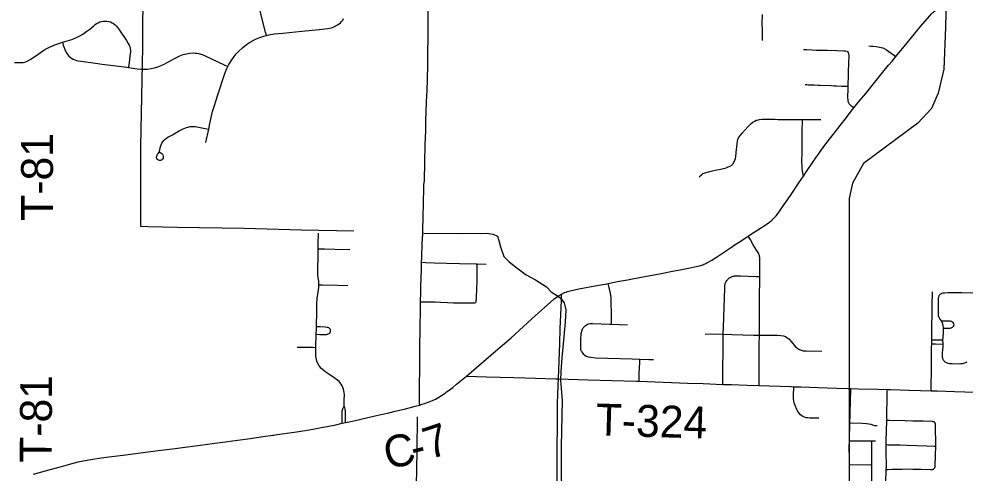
# Model space of a CAD drawing. Extents: x 0 to 680, y 0 to 834.
# Drawn here: x 268.3 to 333.1, y 304.5 to 335.6 of the extents above; entities that cross this region are included whole.
import ezdxf

# ---------------------------------------------------------------- set-up
doc = ezdxf.new("R2010")
doc.units = 0
for name, color, linetype in [('GM_X_City_Street', 7, 'Continuous'), ('GM_X_County_Road', 7, 'Continuous'), ('GM_X_County_Road_Text', 7, 'Continuous'), ('GM_X_Minor_River', 7, 'Continuous'), ('GM_X_Rail_Line', 7, 'Continuous'), ('GM_X_Township_Road', 7, 'Continuous'), ('GM_X_Township_Road_Text', 7, 'Continuous')]:
    doc.layers.add(name, color=color, linetype=linetype)

msp = doc.modelspace()

# ---------------------------------------------------------------- linework, layer by layer
at = {"layer": 'GM_X_City_Street'}
msp.add_line((326.659, 306.718), (326.942, 306.715), dxfattribs=at)
for points in [[(285.264, 334.424), (285.207, 334.647), (284.771, 336.356)], [(268.025, 332.57), (268.505, 332.574), (268.622, 332.582), (268.734, 332.602), (268.844, 332.638), (268.951, 332.684), (269.156, 332.801), (269.651, 333.136), (270.044, 333.413), (270.251, 333.538), (270.467, 333.648), (270.801, 333.787), (271.143, 333.904), (271.308, 333.956), (271.943, 334.157), (272.275, 334.287), (272.489, 334.39), (272.695, 334.507), (272.99, 334.707), (273.177, 334.854), (273.449, 335.09), (273.544, 335.166), (273.645, 335.236), (273.752, 335.297), (273.865, 335.346), (273.984, 335.382), (274.107, 335.403), (274.231, 335.41), (274.354, 335.403), (274.477, 335.382), (274.595, 335.345), (274.709, 335.294), (274.815, 335.231), (274.913, 335.155), (275.002, 335.069), (275.082, 334.976), (275.222, 334.777), (275.692, 334.08), (275.816, 333.871), (275.869, 333.761), (275.912, 333.645), (275.941, 333.525), (275.957, 333.403), (275.957, 333.28), (275.931, 333.037), (275.866, 332.563), (275.854, 332.444), (275.833, 332.23)], [(281.132, 327.117), (281.325, 328.027), (281.404, 328.403), (281.586, 329.219), (281.681, 329.564), (281.941, 330.359), (282.43, 331.834), (282.561, 332.167), (282.626, 332.302), (282.664, 332.383), (282.846, 332.691), (283.052, 332.985), (283.204, 333.17), (283.368, 333.343), (283.632, 333.586), (283.913, 333.809), (284.11, 333.944), (284.315, 334.065), (284.529, 334.172), (284.749, 334.265), (285.089, 334.38), (285.264, 334.424), (285.436, 334.467), (285.789, 334.528), (286.384, 334.589), (287.692, 334.72), (288.882, 334.833), (289.475, 334.901), (289.71, 334.947), (289.823, 334.984), (289.932, 335.033), (290.14, 335.15), (290.237, 335.22), (290.327, 335.298), (290.41, 335.385), (290.484, 335.479), (290.548, 335.579)], [(319.2, 334.091), (319.2, 334.793), (319.196, 335.228), (319.212, 335.865)], [(271.308, 333.956), (271.371, 333.752), (271.407, 333.638), (271.489, 333.412), (271.542, 333.304), (271.603, 333.201), (271.674, 333.105), (271.754, 333.016), (271.843, 332.935), (271.94, 332.866), (272.044, 332.807), (272.155, 332.76), (272.269, 332.724), (272.386, 332.697), (272.742, 332.647), (273.57, 332.525), (274.03, 332.465), (275.713, 332.247), (275.833, 332.23), (276.425, 332.146), (276.663, 332.119), (276.902, 332.113), (277.141, 332.128), (277.379, 332.16), (277.614, 332.208), (277.844, 332.275), (278.066, 332.364), (278.281, 332.471), (279.019, 332.871), (279.341, 333.031), (279.564, 333.118), (279.679, 333.153), (279.796, 333.179), (280.033, 333.213), (280.272, 333.226), (280.392, 333.222), (280.511, 333.209), (280.63, 333.189), (280.862, 333.129), (281.084, 333.04), (282.382, 332.419), (282.626, 332.302)], [(322.008, 333.474), (322.245, 333.461), (322.604, 333.442), (322.903, 333.427), (323.625, 333.416), (324.285, 333.389), (324.765, 333.376), (324.881, 333.364), (324.991, 333.34), (325.035, 333.316), (325.059, 333.294)], [(326.484, 333.705), (326.634, 333.699), (326.751, 333.693), (326.988, 333.669), (327.337, 333.612), (327.446, 333.581), (327.544, 333.536), (327.688, 333.448), (327.853, 333.329), (328.022, 333.207), (328.234, 333.054), (328.331, 332.984)], [(325.464, 329.471), (325.317, 329.577), (325.261, 329.618), (325.222, 329.654), (325.182, 329.703), (325.146, 329.756), (325.116, 329.807), (325.092, 329.861), (325.073, 329.917), (325.061, 330.019), (325.055, 330.17), (325.055, 330.385), (325.064, 330.597), (325.07, 330.954), (325.086, 331.747), (325.096, 332.086), (325.111, 332.402), (325.117, 332.683), (325.127, 332.866), (325.129, 333.04), (325.124, 333.185), (325.098, 333.248), (325.059, 333.294)], [(322.129, 331.073), (322.246, 331.064), (322.347, 331.061), (322.451, 331.058), (322.62, 331.051), (322.732, 331.048), (323.017, 331.038), (323.133, 331.032), (323.9, 330.995), (324.082, 330.991), (324.265, 330.985), (324.609, 330.969), (324.979, 330.957), (325.07, 330.954)], [(314.875, 324.765), (315.055, 324.922), (315.136, 324.979), (315.223, 325.022), (315.279, 325.042), (315.507, 325.112), (315.972, 325.222), (316.442, 325.31), (316.713, 325.387), (316.865, 325.434), (316.932, 325.469), (317.034, 325.521), (317.082, 325.554), (317.127, 325.591), (317.168, 325.634), (317.205, 325.68), (317.268, 325.782), (317.318, 325.89), (317.353, 326.004), (317.376, 326.122), (317.411, 326.418), (317.476, 327.012), (317.502, 327.189), (317.531, 327.305), (317.575, 327.416), (317.632, 327.52), (317.702, 327.617), (317.818, 327.753), (318.222, 328.194), (318.393, 328.359), (318.574, 328.514), (318.675, 328.577), (318.783, 328.626), (318.84, 328.643), (319.014, 328.685), (319.189, 328.709), (319.36, 328.709), (319.559, 328.704), (319.841, 328.705), (320.08, 328.7), (320.259, 328.691), (320.464, 328.69), (320.851, 328.682), (321.139, 328.685), (321.437, 328.676), (321.636, 328.676), (321.797, 328.671), (321.949, 328.671), (322.008, 328.671), (322.118, 328.674), (322.347, 328.683), (322.513, 328.676), (322.692, 328.681), (322.825, 328.681), (323.058, 328.686), (323.195, 328.681)], [(322.012, 324.817), (321.977, 325.032), (321.929, 325.327), (321.915, 325.449), (321.906, 325.811), (321.921, 326.449), (321.921, 326.786), (321.921, 327.027), (321.926, 327.392), (321.93, 328.041), (321.948, 328.41), (321.948, 328.528), (321.949, 328.671)], [(277.944, 326.458), (278.047, 326.391), (278.104, 326.348), (278.147, 326.306), (278.171, 326.269), (278.187, 326.232), (278.202, 326.154), (278.202, 326.085), (278.191, 326.037), (278.16, 325.977), (278.122, 325.941), (278.077, 325.907), (278.018, 325.884), (277.952, 325.88), (277.902, 325.891), (277.844, 325.92), (277.804, 325.957), (277.772, 326.007), (277.756, 326.063), (277.752, 326.125), (277.765, 326.182), (277.784, 326.236), (277.818, 326.287), (277.887, 326.385), (277.926, 326.443), (277.946, 326.488), (277.979, 326.602), (277.994, 326.72), (278.02, 326.836), (278.06, 326.948), (278.113, 327.055), (278.179, 327.153), (278.256, 327.244), (278.341, 327.327), (278.433, 327.403), (278.532, 327.469), (278.845, 327.641), (279.26, 327.875), (279.577, 328.039), (279.796, 328.133), (279.91, 328.167), (280.026, 328.191), (280.145, 328.204), (280.264, 328.207), (280.382, 328.201), (280.5, 328.186), (281.085, 328.073), (281.325, 328.027)], [(290.588, 309.082), (290.596, 309.548), (290.602, 309.846), (290.59, 310.025), (290.57, 310.143), (290.54, 310.258), (290.498, 310.37), (290.446, 310.477), (290.385, 310.58), (290.315, 310.677), (290.236, 310.766), (290.148, 310.846), (289.906, 311.022), (289.46, 311.321), (289.265, 311.46), (289.078, 311.608), (288.994, 311.692), (288.92, 311.786), (288.854, 311.886), (288.768, 312.043), (288.72, 312.152), (288.685, 312.266), (288.661, 312.383), (288.646, 312.501), (288.642, 312.621), (288.652, 312.979), (288.652, 313.104), (288.653, 313.397), (288.668, 313.755), (288.676, 313.999), (288.689, 314.351), (288.691, 314.509), (288.709, 315.605), (288.723, 316.082), (288.748, 316.439), (288.783, 316.735), (288.833, 317.029), (288.851, 317.208), (288.856, 317.382), (288.858, 317.446), (288.85, 317.625), (288.814, 317.861), (288.79, 318.039), (288.785, 318.158), (288.804, 319.59), (288.802, 319.71), (288.805, 319.769), (288.807, 319.851), (288.814, 320.187), (288.832, 320.903)], [(318.992, 313.929), (319.001, 314.973), (319.014, 316.349), (319.018, 317.938), (319.029, 318.762), (319.033, 319.094), (319.031, 319.164), (319.026, 319.237), (319.014, 319.306), (319, 319.368), (318.983, 319.427), (318.958, 319.486), (318.931, 319.545), (318.904, 319.595), (318.802, 319.756), (318.581, 320.116), (318.355, 320.495), (318.226, 320.711)], [(288.807, 319.851), (289.06, 319.848), (289.238, 319.846), (289.953, 319.824), (290.966, 319.805)], [(316.498, 310.577), (316.499, 310.786), (316.504, 311.659), (316.51, 312.859), (316.518, 313.802), (316.523, 314.013), (316.535, 314.49), (316.582, 315.826), (316.625, 317.161), (316.64, 317.347), (316.65, 317.407), (316.662, 317.459), (316.68, 317.516), (316.701, 317.565), (316.728, 317.616), (316.757, 317.664), (316.789, 317.708), (316.828, 317.753), (316.867, 317.793), (316.911, 317.83), (316.95, 317.859), (316.988, 317.883), (317.035, 317.909), (317.087, 317.933), (317.144, 317.954), (317.195, 317.969), (317.243, 317.977), (317.284, 317.986), (317.352, 317.992), (317.424, 317.994), (317.708, 317.993), (318.781, 317.947), (319.018, 317.938)], [(288.856, 317.382), (289.106, 317.375), (290.12, 317.349), (290.836, 317.335)], [(308.866, 314.695), (308.868, 314.797), (308.875, 315.352), (308.864, 316.26), (308.848, 316.501), (308.801, 316.81), (308.699, 317.282), (308.657, 317.477)], [(305.255, 310.947), (305.272, 311.592), (305.333, 313.342), (305.375, 314.383), (305.434, 315.818), (305.456, 316.342), (305.454, 316.746)], [(330.749, 310.137), (330.751, 310.265), (330.769, 311.71), (330.777, 313.082), (330.783, 313.349), (330.788, 313.616), (330.796, 313.977), (330.818, 315.947), (330.829, 316.902)], [(333.604, 316.815), (332.848, 316.825), (331.892, 316.823), (331.655, 316.82), (331.541, 316.805), (331.486, 316.789), (331.435, 316.77), (331.389, 316.742), (331.346, 316.71), (331.313, 316.67), (331.284, 316.625), (331.249, 316.523), (331.238, 316.47), (331.226, 316.354), (331.223, 315.756), (331.223, 315.397), (331.232, 315.283), (331.263, 315.175), (331.315, 315.077), (331.345, 315.028), (331.447, 314.899), (331.509, 314.775), (331.533, 314.717), (331.552, 314.594), (331.562, 314.428), (331.566, 314.353), (331.562, 314.111), (331.539, 313.79), (331.535, 313.624), (331.545, 313.329)], [(306.817, 312.832), (306.788, 312.924), (306.777, 313.024), (306.774, 313.179), (306.783, 313.635), (306.806, 314.044), (306.836, 314.208), (306.886, 314.343), (306.948, 314.445), (307.027, 314.536), (307.096, 314.594), (307.161, 314.64)], [(307.161, 314.64), (307.217, 314.671), (307.291, 314.702), (307.407, 314.729), (307.573, 314.742), (308.762, 314.699), (308.866, 314.695), (309.974, 314.654)], [(331.562, 314.428), (331.764, 314.423), (331.939, 314.419), (332.056, 314.427), (332.114, 314.439), (332.169, 314.458), (332.219, 314.487), (332.261, 314.526), (332.292, 314.575), (332.309, 314.631), (332.312, 314.655), (332.309, 314.689), (332.302, 314.716), (332.292, 314.745), (332.261, 314.794), (332.219, 314.834), (332.168, 314.862), (332.113, 314.88), (332.055, 314.892), (331.938, 314.901), (331.822, 314.901), (331.447, 314.899)], [(288.676, 313.999), (288.908, 313.994), (289.265, 313.986), (289.385, 313.991), (289.443, 314), (289.5, 314.019), (289.553, 314.047), (289.598, 314.085), (289.632, 314.133), (289.652, 314.189), (289.657, 314.247), (289.645, 314.303), (289.618, 314.355), (289.577, 314.397), (289.528, 314.429), (289.473, 314.453), (289.415, 314.469), (289.296, 314.484), (288.939, 314.499), (288.691, 314.509)], [(315.29, 314.04), (316.523, 314.013), (317.109, 313.991), (318.615, 313.936), (318.992, 313.929)], [(318.981, 310.492), (318.98, 310.65), (318.979, 310.92), (318.983, 311.491), (318.982, 311.8), (318.97, 312.775), (318.979, 313.301), (318.992, 313.929)], [(318.992, 313.929), (320.226, 313.942), (320.467, 313.926), (320.635, 313.893), (320.775, 313.843), (320.884, 313.783), (321, 313.69), (321.164, 313.513), (321.472, 313.152), (321.592, 313.044), (321.726, 312.957), (321.852, 312.904), (321.985, 312.874), (322.206, 312.861), (323.261, 312.851)], [(330.783, 313.349), (331.038, 313.342), (331.545, 313.329)], [(330.788, 313.616), (330.986, 313.616), (331.182, 313.615), (331.312, 313.618), (331.535, 313.624)], [(331.545, 313.329), (331.54, 313.092), (331.524, 312.982), (331.496, 312.686), (331.493, 312.569), (331.502, 312.455), (331.514, 312.4), (331.531, 312.347), (331.553, 312.296), (331.58, 312.247), (331.612, 312.201), (331.649, 312.158), (331.69, 312.12), (331.734, 312.087), (331.782, 312.059), (331.833, 312.037), (331.886, 312.02), (331.998, 312.001), (332.174, 311.994), (332.651, 311.988), (332.767, 311.995), (332.882, 312.013), (333.052, 312.058), (333.218, 312.117)], [(287.377, 313.125), (287.948, 313.115), (288.43, 313.108), (288.652, 313.104)], [(306.817, 312.832), (306.874, 312.749), (306.946, 312.663), (307.048, 312.578), (307.147, 312.512), (307.279, 312.459), (307.466, 312.425), (307.797, 312.398), (310.302, 312.323), (310.819, 312.305), (311.421, 312.283), (311.754, 312.271)], [(310.759, 310.784), (310.771, 311.32), (310.808, 312.09), (310.819, 312.305)], [(323.06, 308.27), (322.454, 308.27), (322.318, 308.281), (322.201, 308.297), (322.085, 308.326), (321.975, 308.372), (321.895, 308.423), (321.806, 308.503), (321.712, 308.611), (321.631, 308.73), (321.564, 308.856), (321.454, 309.121), (321.381, 309.323), (321.36, 309.402), (321.344, 309.484), (321.334, 309.58), (321.338, 309.843), (321.354, 310.36), (321.355, 310.413)], [(325.186, 307.936), (325.201, 308.517), (325.238, 309.566), (325.25, 310.067), (325.255, 310.284)], [(327.708, 308.113), (327.749, 310.099), (327.751, 310.222)], [(290.455, 307.913), (290.453, 308.18), (290.451, 308.561), (290.455, 308.746), (290.488, 308.898), (290.588, 309.082)], [(290.678, 307.962), (290.678, 308.263), (290.678, 308.689), (290.664, 308.903), (290.64, 308.983), (290.588, 309.082)], [(325.155, 306.724), (325.156, 306.751), (325.186, 307.936)], [(325.186, 307.936), (325.232, 307.936), (326.018, 307.925), (326.327, 307.909), (326.492, 307.886), (326.63, 307.851), (326.809, 307.785), (326.875, 307.771), (326.961, 307.759), (327.045, 307.76)], [(327.676, 306.455), (327.678, 306.709), (327.708, 308.113)], [(331.06, 306.359), (331.06, 306.424), (331.059, 306.56), (331.052, 307.599), (331.051, 307.75), (331.049, 307.826), (331.048, 307.853), (331.043, 307.879), (331.035, 307.903), (331.024, 307.925), (331.008, 307.949), (330.991, 307.968), (330.97, 307.988), (330.946, 308.004), (330.921, 308.017), (330.894, 308.025), (330.845, 308.036), (330.808, 308.039), (330.193, 308.053), (329.502, 308.067), (328.978, 308.082), (327.905, 308.108), (327.708, 308.113)], [(325.158, 305.093), (325.152, 305.558), (325.149, 306.226), (325.155, 306.724)], [(325.155, 306.724), (325.855, 306.721), (326.659, 306.718)], [(326.659, 306.718), (326.663, 306.305), (326.674, 305.077)], [(327.68, 304.766), (327.684, 304.913), (327.686, 305.318), (327.678, 305.6), (327.671, 305.925), (327.676, 306.455)], [(327.676, 306.455), (327.775, 306.453), (328.62, 306.433), (329.074, 306.424), (330.437, 306.382), (330.959, 306.362), (331.06, 306.359)], [(327.68, 304.766), (327.794, 304.767), (328.052, 304.769), (328.513, 304.776), (328.761, 304.785), (329.054, 304.795), (329.489, 304.79), (330.06, 304.771), (330.677, 304.754), (330.759, 304.753), (330.791, 304.754), (330.823, 304.756), (330.854, 304.763), (330.883, 304.774), (330.91, 304.786), (330.934, 304.799), (330.957, 304.818), (330.976, 304.84), (330.999, 304.882), (331.008, 304.912), (331.013, 304.941), (331.02, 305.004), (331.048, 305.71), (331.06, 306.359)], [(325.158, 305.093), (325.199, 305.093), (326.587, 305.078), (326.674, 305.077)], [(325.175, 303.124), (325.169, 303.864), (325.163, 304.604), (325.158, 305.093)], [(326.674, 305.077), (326.67, 304.302), (326.666, 303.456), (326.666, 303.269), (326.664, 303.139)], [(327.558, 301.905), (327.562, 302.097), (327.578, 302.933), (327.592, 303.265), (327.626, 303.746), (327.666, 304.455), (327.679, 304.715), (327.68, 304.766)]]:
    msp.add_lwpolyline(points, dxfattribs=at)
at = {"layer": 'GM_X_County_Road'}
msp.add_line((285.763, 307.102), (285.872, 307.118), dxfattribs=at)
for points in [[(328.331, 332.984), (329.099, 333.919), (329.395, 334.289), (330.022, 335.039), (330.626, 335.745), (330.773, 335.899), (330.841, 335.962), (330.913, 336.023), (330.985, 336.077), (331.05, 336.125), (331.108, 336.165)], [(325.464, 329.471), (325.65, 329.707), (325.85, 329.952), (326.268, 330.468), (326.615, 330.894), (327.357, 331.806), (327.84, 332.39), (328.069, 332.665), (328.331, 332.984)], [(322.012, 324.817), (322.214, 325.117), (322.643, 325.755), (322.907, 326.131), (323.032, 326.304), (323.184, 326.517), (323.548, 327.018), (324.131, 327.773), (324.513, 328.262), (324.952, 328.822), (325.286, 329.245), (325.464, 329.471)], [(318.226, 320.711), (318.382, 320.814), (318.882, 321.138), (319.448, 321.495), (319.684, 321.661), (319.854, 321.797), (319.994, 321.931), (320.138, 322.095), (320.298, 322.305), (320.622, 322.78), (320.914, 323.2), (321.21, 323.626), (321.7, 324.353), (322.012, 324.817)], [(308.657, 317.477), (309.298, 317.598), (309.979, 317.718), (311.03, 317.922), (311.662, 318.045), (312.269, 318.164), (313.042, 318.308), (313.582, 318.408), (314.143, 318.521), (314.562, 318.604), (314.89, 318.682), (315.12, 318.753), (315.199, 318.784), (315.277, 318.816), (315.489, 318.921), (315.743, 319.068), (316.063, 319.279), (316.537, 319.6), (317.015, 319.912), (317.349, 320.139), (317.567, 320.281), (318.163, 320.67), (318.226, 320.711)], [(305.454, 316.746), (305.663, 316.846), (305.768, 316.888), (305.861, 316.921), (306.041, 316.971), (306.647, 317.101), (307.866, 317.333), (308.547, 317.457), (308.657, 317.477)], [(298.952, 311.127), (299.79, 311.862), (300.455, 312.427), (300.97, 312.865), (302.005, 313.767), (302.854, 314.532), (303.675, 315.273), (304.283, 315.821), (304.675, 316.169), (304.96, 316.42), (305.05, 316.493), (305.149, 316.565), (305.286, 316.651), (305.454, 316.746)], [(295.753, 309.161), (295.86, 309.19), (296.154, 309.282), (296.407, 309.373), (296.625, 309.464), (296.838, 309.571), (297.071, 309.703), (297.318, 309.863), (297.497, 309.983), (297.593, 310.055), (297.707, 310.14), (298.01, 310.372), (298.274, 310.578), (298.952, 311.127)], [(292.802, 308.439), (293.217, 308.533), (293.636, 308.627), (294.078, 308.733), (294.775, 308.9), (295.537, 309.103), (295.753, 309.161)], [(290.78, 307.984), (290.814, 307.992), (291.244, 308.081), (292.204, 308.304), (292.802, 308.439)], [(285.872, 307.118), (287.162, 307.302), (287.474, 307.347), (288.181, 307.459), (288.557, 307.529), (289.142, 307.639), (289.168, 307.645), (290.007, 307.816), (290.455, 307.913)], [(290.455, 307.913), (290.678, 307.962), (290.78, 307.984)], [(269.337, 304.437), (270.562, 304.776), (271.235, 304.962), (271.889, 305.142), (272.396, 305.275), (272.724, 305.344), (273.401, 305.466), (273.967, 305.547), (274.488, 305.612), (275.46, 305.732), (277.683, 306.027), (279.032, 306.203), (279.695, 306.283), (280.571, 306.4), (281.068, 306.466), (281.73, 306.556), (282.463, 306.658), (282.936, 306.72), (284.001, 306.863), (285.042, 307.003), (285.713, 307.095), (285.763, 307.102)]]:
    msp.add_lwpolyline(points, dxfattribs=at)
at = {"layer": 'GM_X_Minor_River'}
for points in [[(276.813, 345.396), (276.806, 338.087), (276.778, 333.623), (276.641, 326.854), (276.654, 321.383), (277.164, 321.367), (279.16, 321.332), (283.734, 321.245), (287.668, 321.13), (291.252, 321.076)], [(296.03, 320.901), (298.347, 320.879), (300.314, 320.903), (300.78, 320.843), (301.071, 320.711), (301.172, 320.419), (301.287, 319.981), (301.504, 319.309), (301.881, 318.958), (302.317, 318.606), (303.03, 318.064), (303.67, 317.712), (304.426, 317.243), (304.76, 316.907), (305.254, 316.584), (305.4, 316.453), (305.647, 316.145), (305.747, 315.664), (305.701, 314.832), (305.64, 314.088), (305.58, 313.345), (305.475, 312.382), (305.399, 311.463), (305.397, 310.836), (305.495, 309.464), (305.442, 306.343), (305.457, 301.645)], [(294.448, 231.644), (294.646, 239.097), (294.587, 243.59), (294.76, 252.516), (294.959, 260.451), (295.068, 267.555), (295.172, 273.083), (295.262, 278.699), (295.353, 284.709), (295.471, 290.048), (295.56, 295.431), (295.613, 298.582), (295.549, 301.5), (295.541, 303.615), (295.592, 306.022), (295.599, 308.356)]]:
    msp.add_lwpolyline(points, dxfattribs=at)
at = {"layer": 'GM_X_Rail_Line'}
msp.add_lwpolyline([(332.297, 358.476), (331.74, 334.991), (331.623, 332.119), (331.235, 330.489), (330.77, 329.441), (329.838, 328.432), (326.114, 325.676), (325.377, 324.318), (325.144, 323.27), (325.144, 290.084), (324.626, 272.539), (324.407, 251.582), (324.019, 224.102), (323.747, 191.887)], dxfattribs=at)
at = {"layer": 'GM_X_Township_Road'}
for p, q in [((299.693, 318.819), (300.309, 318.801)), ((321.171, 310.419), (321.355, 310.413)), ((330.749, 310.137), (331.115, 310.128))]:
    msp.add_line(p, q, dxfattribs=at)
for points in [[(296.036, 323.991), (296.036, 324.029), (296.04, 324.204), (296.076, 324.507), (296.103, 325.758), (296.139, 326.95), (296.167, 327.903), (296.182, 328.559), (296.224, 329.869), (296.262, 330.703), (296.278, 331.359), (296.3, 332.431), (296.318, 333.266), (296.333, 334.28), (296.332, 334.463), (296.33, 334.817), (296.331, 334.895), (296.334, 335.472), (296.326, 336.247), (296.344, 336.782), (296.35, 336.983)], [(295.961, 320.867), (295.967, 321.027), (295.974, 321.187), (295.997, 321.971), (296.036, 323.991)], [(295.888, 318.922), (295.9, 319.248), (295.933, 320.215), (295.961, 320.867)], [(295.819, 316.224), (295.826, 316.884), (295.835, 317.225), (295.854, 317.888), (295.868, 318.353), (295.888, 318.922)], [(295.888, 318.922), (296.161, 318.913), (296.752, 318.893), (297.584, 318.87), (298.476, 318.846), (299.604, 318.822), (299.693, 318.819)], [(299.598, 316.175), (299.617, 316.207), (299.627, 316.26), (299.633, 316.475), (299.642, 316.674), (299.656, 316.949), (299.666, 317.114), (299.67, 317.28), (299.675, 317.465), (299.68, 317.659), (299.68, 317.839), (299.684, 317.996), (299.694, 318.261), (299.694, 318.701), (299.693, 318.819)], [(295.753, 309.161), (295.749, 309.304), (295.743, 309.468), (295.744, 309.645), (295.739, 310.127), (295.745, 310.545), (295.763, 311.561), (295.768, 312.697), (295.771, 313.113), (295.77, 313.473), (295.78, 314.008), (295.779, 314.359), (295.814, 315.799), (295.819, 316.224)], [(295.819, 316.224), (295.992, 316.222), (296.165, 316.219), (296.465, 316.207), (296.812, 316.208), (297.168, 316.19), (297.645, 316.174), (298.076, 316.156), (298.602, 316.151), (299.01, 316.146), (299.248, 316.144), (299.513, 316.15), (299.537, 316.153), (299.598, 316.175)], [(298.952, 311.127), (300.331, 311.098), (302.188, 311.047), (303.667, 310.998), (305.075, 310.954), (305.255, 310.947)], [(305.097, 290.958), (305.101, 291.354), (305.097, 293.503), (305.129, 298.875), (305.155, 301.382), (305.167, 304.725), (305.193, 309.262), (305.226, 310.49), (305.255, 310.947)], [(305.255, 310.947), (307.269, 310.89), (310.584, 310.791), (310.759, 310.784)], [(310.759, 310.784), (314.068, 310.664), (315.153, 310.626), (316.498, 310.577)], [(316.498, 310.577), (317.094, 310.555), (318.167, 310.519), (318.981, 310.492)], [(318.981, 310.492), (321.134, 310.42), (321.171, 310.419)], [(321.355, 310.413), (321.837, 310.396), (323.007, 310.362), (324.262, 310.317), (325.08, 310.288), (325.255, 310.284)], [(325.255, 310.284), (325.768, 310.271), (327.104, 310.241), (327.751, 310.222), (327.959, 310.215), (329.211, 310.175), (330.027, 310.155), (330.749, 310.137)], [(331.115, 310.128), (331.152, 310.127), (332.355, 310.093)], [(332.355, 310.093), (333.062, 310.066), (333.748, 310.047), (334.409, 310.028), (335.386, 310.008), (335.673, 309.999), (335.974, 309.985), (338.833, 309.863)]]:
    msp.add_lwpolyline(points, dxfattribs=at)

# ---------------------------------------------------------------- texts
at = {"layer": 'GM_X_County_Road_Text'}
for s, rotation, p in [('7', 18.23249, (296.42, 305.418)), ('C', 11.98735, (293.547, 304.76)), ('-', 14.03522, (295.383, 305.152))]:
    msp.add_text(s, height=2.182, rotation=rotation, dxfattribs=at).set_placement(p)
at = {"layer": 'GM_X_Township_Road_Text'}
for s, rotation, p in [('T-81', 90, (270.664, 321.756)), ('T-81', 89.64834, (270.568, 305.209)), ('T-324', 358.315, (307.776, 307.091))]:
    msp.add_text(s, height=2.1818, rotation=rotation, dxfattribs=at).set_placement(p)

doc.saveas('drawing.dxf')
